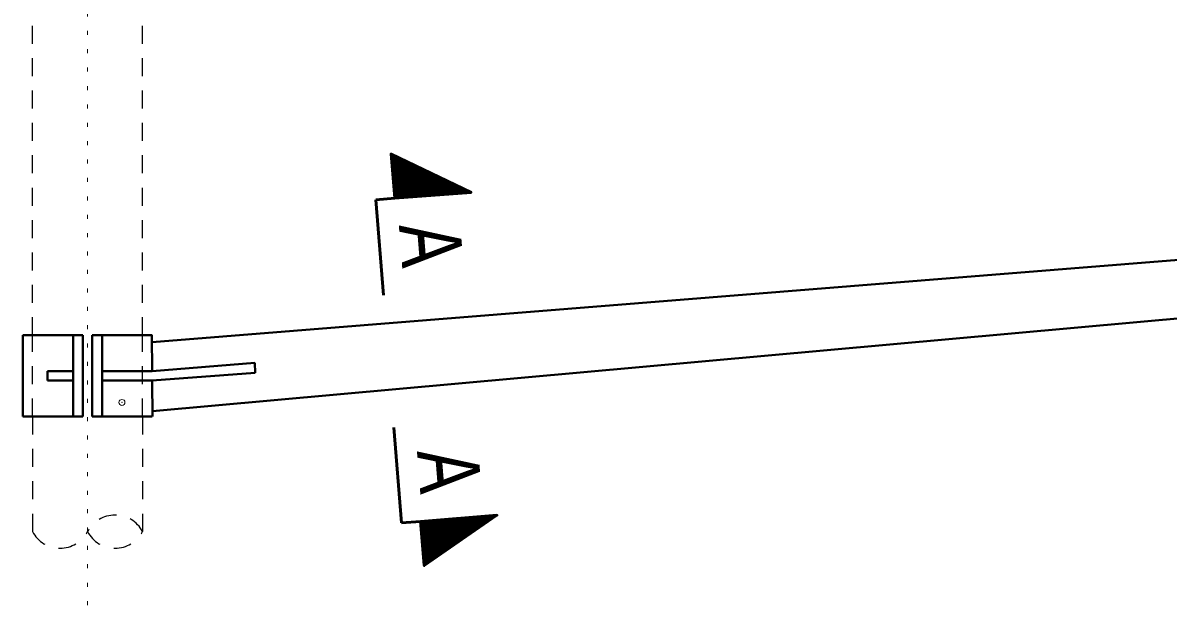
# Model space of a CAD drawing. Extents: x 312583 to 312854, y 144419 to 144597.
# Drawn here: x 312708.98 to 312737.61, y 144536.85 to 144551.41 of the extents above; entities that cross this region are included whole.
import ezdxf
from ezdxf.enums import TextEntityAlignment as Align

# ---------------------------------------------------------------- set-up
doc = ezdxf.new("R2010")
doc.units = 0
doc.header["$LTSCALE"] = 0.3
doc.header["$PDMODE"] = 32
doc.header["$PDSIZE"] = 0.15
doc.linetypes.add('DOTTED', pattern=[1.5, 0.3, -1.2])
doc.linetypes.add('SHORT_DASHED', pattern=[2.7, 1.5, -1.2])
doc.layers.add('1', color=7, linetype='Continuous', lineweight=35)
doc.layers.add('2', color=7, linetype='Continuous', lineweight=13)

msp = doc.modelspace()

# ---------------------------------------------------------------- linework, layer by layer
at = {"layer": '1', "linetype": 'DOTTED', "lineweight": 13}
msp.add_line((312710.5956, 144536.8489), (312710.5956, 144562.3636), dxfattribs=at)
at = {"layer": '1', "linetype": 'SHORT_DASHED', "lineweight": 25}
for p, q in [((312709.2156, 144543.5956), (312709.2156, 144555.9389)), ((312711.9679, 144543.5956), (312711.9679, 144555.9389)), ((312709.2156, 144541.5639), (312709.2156, 144543.5956)), ((312711.9679, 144541.5639), (312711.9679, 144543.5956)), ((312709.2156, 144541.5639), (312709.2156, 144538.6889)), ((312711.9679, 144541.5639), (312711.9679, 144538.6889))]:
    msp.add_line(p, q, dxfattribs=at)
at = {"layer": '1', "lineweight": 40}
for p, q in [((312712.2132, 144543.4269), (312791.0956, 144549.7443)), ((312712.2209, 144541.6943), (312791.0956, 144548.8319)), ((312708.9779, 144543.5956), (312710.4729, 144543.5956)), ((312708.9779, 144542.5759), (312708.9779, 144543.5956)), ((312710.2352, 144542.5759), (312710.2352, 144543.5956)), ((312710.4729, 144542.5759), (312710.4729, 144543.5956)), ((312712.2132, 144543.5956), (312710.7106, 144543.5956)), ((312710.7106, 144542.5759), (312710.7106, 144543.5956)), ((312710.9559, 144542.5759), (312710.9559, 144543.5956)), ((312712.1979, 144543.5956), (312712.2132, 144542.6986)), ((312709.5912, 144542.6986), (312709.5912, 144542.4609)), ((312710.2352, 144542.6986), (312709.5912, 144542.6986)), ((312712.2132, 144542.6986), (312710.9559, 144542.6986)), ((312712.2132, 144542.6986), (312714.7739, 144542.9056)), ((312712.2132, 144542.4609), (312714.7892, 144542.6603)), ((312714.7739, 144542.9056), (312714.7892, 144542.6603)), ((312708.9779, 144542.5759), (312708.9779, 144541.5639)), ((312710.2352, 144542.4609), (312709.5912, 144542.4609)), ((312710.2352, 144542.5759), (312710.2352, 144541.5639)), ((312710.4729, 144542.5759), (312710.4729, 144541.5639)), ((312710.7106, 144542.5759), (312710.7106, 144541.5639)), ((312710.9559, 144542.5759), (312710.9559, 144541.5639)), ((312712.2286, 144542.4609), (312710.9559, 144542.4609)), ((312712.2132, 144542.4533), (312712.2209, 144541.5639))]:
    msp.add_line(p, q, dxfattribs=at)
at = {"layer": '1'}
for p, q in [((312718.1856, 144548.0959), (312718.2009, 144548.1113)), ((312718.1932, 144548.0499), (312718.2239, 144548.1036)), ((312718.2009, 144547.9963), (312718.2469, 144548.0959)), ((312718.2009, 144547.9503), (312718.2699, 144548.0806)), ((312718.2086, 144547.8966), (312718.2929, 144548.0729)), ((312718.2086, 144547.8583), (312718.3082, 144548.0576)), ((312718.2162, 144547.8046), (312718.3312, 144548.0576)), ((312718.2162, 144547.7586), (312718.3542, 144548.0423)), ((312718.2162, 144547.7126), (312718.3696, 144548.0346)), ((312718.2239, 144547.6666), (312718.4002, 144548.0193)), ((312718.2316, 144547.6129), (312718.4156, 144548.0116)), ((312718.2316, 144547.5669), (312718.4462, 144548.0039)), ((312718.2392, 144547.5209), (312718.4692, 144547.9963)), ((312718.2392, 144547.4673), (312718.4846, 144547.9809)), ((312718.2469, 144547.4213), (312718.5076, 144547.9733)), ((312718.2469, 144547.3753), (312718.5229, 144547.9579)), ((312718.2546, 144547.3216), (312718.5459, 144547.9503)), ((312718.2546, 144547.2756), (312718.5689, 144547.9426)), ((312718.2622, 144547.2296), (312718.5842, 144547.9273)), ((312718.2622, 144547.1836), (312718.6149, 144547.9119)), ((312718.2699, 144547.1299), (312718.6379, 144547.9119)), ((312718.2699, 144547.0993), (312718.6532, 144547.8966)), ((312718.2776, 144547.0456), (312718.6839, 144547.8889)), ((312718.2929, 144547.0226), (312718.6992, 144547.8736)), ((312718.3236, 144547.0226), (312718.7222, 144547.8736)), ((312718.3542, 144547.0226), (312718.7452, 144547.8583)), ((312718.3772, 144547.0303), (312718.7606, 144547.8506)), ((312718.4079, 144547.0303), (312718.7836, 144547.8353)), ((312718.4309, 144547.0379), (312718.8142, 144547.8276)), ((312718.4616, 144547.0379), (312718.8296, 144547.8199)), ((312718.4846, 144547.0379), (312718.8526, 144547.8123)), ((312718.5152, 144547.0379), (312718.8756, 144547.7969)), ((312718.5459, 144547.0379), (312718.8909, 144547.7816)), ((312718.5689, 144547.0456), (312718.9139, 144547.7739)), ((312718.5996, 144547.0456), (312718.9369, 144547.7663)), ((312718.6302, 144547.0456), (312718.9599, 144547.7509)), ((312718.6532, 144547.0456), (312718.9752, 144547.7433)), ((312718.6839, 144547.0609), (312719.0059, 144547.7279)), ((312718.7146, 144547.0533), (312719.0289, 144547.7279)), ((312718.7376, 144547.0533), (312719.0442, 144547.7126)), ((312718.7606, 144547.0609), (312719.0672, 144547.7049)), ((312718.7912, 144547.0609), (312719.0902, 144547.6896)), ((312718.8219, 144547.0609), (312719.1056, 144547.6819)), ((312718.8449, 144547.0686), (312719.1286, 144547.6743)), ((312718.8756, 144547.0686), (312719.1516, 144547.6666)), ((312718.8986, 144547.0686), (312719.1746, 144547.6513)), ((312718.9216, 144547.0763), (312719.2052, 144547.6436)), ((312718.9522, 144547.0763), (312719.2206, 144547.6359)), ((312718.9752, 144547.0763), (312719.2436, 144547.6206)), ((312719.0059, 144547.0763), (312719.2666, 144547.6129)), ((312719.0366, 144547.0839), (312719.2819, 144547.5976)), ((312719.0596, 144547.0839), (312719.3049, 144547.5899)), ((312719.0902, 144547.0839), (312719.3279, 144547.5823)), ((312719.1209, 144547.0839), (312719.3432, 144547.5746)), ((312719.1439, 144547.0916), (312719.3739, 144547.5593)), ((312719.1746, 144547.0916), (312719.3969, 144547.5516)), ((312719.2052, 144547.0916), (312719.4122, 144547.5439)), ((312719.2282, 144547.0993), (312719.4352, 144547.5363)), ((312719.2512, 144547.0993), (312719.4582, 144547.5209)), ((312719.2819, 144547.0993), (312719.4812, 144547.5133)), ((312719.3126, 144547.0993), (312719.4966, 144547.4979)), ((312719.3432, 144547.1069), (312719.5196, 144547.4903)), ((312719.3662, 144547.1069), (312719.5426, 144547.4826)), ((312719.3969, 144547.1069), (312719.5656, 144547.4673)), ((312719.4199, 144547.1146), (312719.5886, 144547.4519)), ((312719.4506, 144547.1146), (312719.6116, 144547.4519)), ((312719.4736, 144547.1146), (312719.6269, 144547.4366)), ((312719.5042, 144547.1146), (312719.6499, 144547.4289)), ((312719.5349, 144547.1223), (312719.6729, 144547.4136)), ((312719.5579, 144547.1223), (312719.6882, 144547.4059)), ((312719.5886, 144547.1223), (312719.7189, 144547.3983)), ((312719.6116, 144547.1223), (312719.7419, 144547.3906)), ((312719.6422, 144547.1299), (312719.7649, 144547.3753)), ((312719.6729, 144547.1299), (312719.7879, 144547.3676)), ((312719.6959, 144547.1299), (312719.8032, 144547.3599)), ((312719.7266, 144547.1376), (312719.8262, 144547.3523)), ((312719.7496, 144547.1376), (312719.8492, 144547.3369)), ((312719.7802, 144547.1376), (312719.8646, 144547.3216)), ((312719.8109, 144547.1453), (312719.8876, 144547.3139)), ((312719.8416, 144547.1453), (312719.9106, 144547.3063)), ((312719.8646, 144547.1453), (312719.9336, 144547.2909)), ((312719.8952, 144547.1453), (312719.9566, 144547.2833)), ((312719.9182, 144547.1529), (312719.9796, 144547.2679)), ((312719.9412, 144547.1529), (312720.0026, 144547.2679)), ((312719.9719, 144547.1529), (312720.0179, 144547.2526)), ((312720.0026, 144547.1606), (312720.0409, 144547.2449)), ((312720.0332, 144547.1606), (312720.0639, 144547.2296)), ((312720.0562, 144547.1606), (312720.0792, 144547.2219)), ((312720.0869, 144547.1606), (312720.1099, 144547.2143)), ((312720.1099, 144547.1683), (312720.1329, 144547.2066)), ((312720.1406, 144547.1683), (312720.1482, 144547.1913)), ((312720.1712, 144547.1683), (312720.1712, 144547.1836)), ((312718.9216, 144538.9189), (312719.4659, 144538.1523)), ((312718.9369, 144538.9496), (312719.4736, 144538.1676)), ((312718.9676, 144538.9496), (312719.4966, 144538.1753)), ((312718.9982, 144538.9496), (312719.5196, 144538.1906)), ((312719.0212, 144538.9496), (312719.5349, 144538.1983)), ((312719.0519, 144538.9573), (312719.5579, 144538.2213)), ((312719.0749, 144538.9496), (312719.5809, 144538.2289)), ((312719.1056, 144538.9496), (312719.5962, 144538.2443)), ((312719.1286, 144538.9649), (312719.6116, 144538.2519)), ((312719.1592, 144538.9649), (312719.6346, 144538.2749)), ((312719.1899, 144538.9649), (312719.6499, 144538.2903)), ((312719.2129, 144538.9649), (312719.6729, 144538.2979)), ((312719.2436, 144538.9726), (312719.6959, 144538.3133)), ((312719.2742, 144538.9726), (312719.7189, 144538.3286)), ((312719.2972, 144538.9726), (312719.7342, 144538.3439)), ((312719.3279, 144538.9726), (312719.7496, 144538.3593)), ((312719.3586, 144538.9803), (312719.7726, 144538.3669)), ((312719.3816, 144538.9803), (312719.7879, 144538.3823)), ((312719.4046, 144538.9803), (312719.8109, 144538.3899)), ((312719.4352, 144538.9879), (312719.8339, 144538.4129)), ((312719.4659, 144538.9879), (312719.8492, 144538.4206)), ((312719.4966, 144538.9879), (312719.8722, 144538.4359)), ((312719.5196, 144538.9956), (312719.8952, 144538.4436)), ((312719.5502, 144538.9956), (312719.9029, 144538.4589)), ((312719.5732, 144538.9879), (312719.9336, 144538.4743)), ((312719.6039, 144538.9956), (312719.9489, 144538.4896)), ((312719.6269, 144539.0033), (312719.9719, 144538.5049)), ((312719.6576, 144539.0033), (312719.9949, 144538.5126)), ((312719.6882, 144539.0033), (312720.0102, 144538.5279)), ((312719.7112, 144539.0109), (312720.0332, 144538.5433)), ((312719.7419, 144539.0109), (312720.0562, 144538.5586)), ((312719.7726, 144539.0109), (312720.0639, 144538.5663)), ((312719.7956, 144539.0109), (312720.0869, 144538.5816)), ((312719.8262, 144539.0186), (312720.1099, 144538.5969)), ((312719.8569, 144539.0186), (312720.1252, 144538.6123)), ((312719.8799, 144539.0186), (312720.1482, 144538.6199)), ((312719.9029, 144539.0263), (312720.1712, 144538.6353)), ((312719.9336, 144539.0263), (312720.1942, 144538.6429)), ((312719.9642, 144539.0263), (312720.2096, 144538.6659)), ((312719.9949, 144539.0339), (312720.2249, 144538.6813)), ((312720.0179, 144539.0339), (312720.2479, 144538.6889)), ((312720.0486, 144539.0339), (312720.2632, 144538.7043)), ((312720.0716, 144539.0339), (312720.2862, 144538.7196)), ((312720.1022, 144539.0416), (312720.3092, 144538.7349)), ((312720.1176, 144539.0416), (312720.3246, 144538.7503)), ((312720.1482, 144539.0416), (312720.3476, 144538.7579)), ((312720.1866, 144539.0416), (312720.3629, 144538.7733)), ((312720.2019, 144539.0493), (312720.3782, 144538.7809)), ((312720.2326, 144539.0493), (312720.4089, 144538.8039)), ((312720.2556, 144539.0493), (312720.4242, 144538.8116)), ((312720.2862, 144539.0569), (312720.4472, 144538.8269)), ((312720.3169, 144539.0569), (312720.4702, 144538.8346)), ((312720.3399, 144539.0569), (312720.4856, 144538.8576)), ((312720.3706, 144539.0569), (312720.5086, 144538.8653)), ((312720.3936, 144539.0646), (312720.5239, 144538.8806)), ((312720.4242, 144539.0646), (312720.5392, 144538.8959)), ((312720.4549, 144539.0646), (312720.5622, 144538.9036)), ((312720.4856, 144539.0723), (312720.5852, 144538.9266)), ((312720.5086, 144539.0723), (312720.6006, 144538.9419)), ((312720.5392, 144539.0723), (312720.6236, 144538.9496)), ((312720.5622, 144539.0723), (312720.6389, 144538.9649)), ((312720.5852, 144539.0799), (312720.6619, 144538.9803)), ((312720.6159, 144539.0799), (312720.6772, 144538.9956)), ((312720.6466, 144539.0799), (312720.7002, 144539.0033)), ((312720.6772, 144539.0876), (312720.7232, 144539.0186)), ((312720.7002, 144539.0876), (312720.7386, 144539.0263)), ((312720.7309, 144539.0876), (312720.7616, 144539.0493)), ((312720.7539, 144539.0876), (312720.7846, 144539.0569)), ((312720.7846, 144539.0953), (312720.7922, 144539.0723)), ((312720.8152, 144539.0953), (312720.8152, 144539.0799)), ((312718.9292, 144538.8653), (312719.4352, 144538.1369)), ((312718.9292, 144538.8269), (312719.4199, 144538.1216)), ((312718.9369, 144538.7733), (312719.3969, 144538.1139)), ((312718.9369, 144538.7273), (312719.3739, 144538.0986)), ((312718.9446, 144538.6813), (312719.3586, 144538.0833)), ((312718.9446, 144538.6353), (312719.3356, 144538.0679)), ((312718.9522, 144538.5893), (312719.3126, 144538.0526)), ((312718.9522, 144538.5433), (312719.3049, 144538.0373)), ((312718.9599, 144538.4973), (312719.2819, 144538.0296)), ((312718.9599, 144538.4436), (312719.2666, 144538.0143)), ((312718.9676, 144538.3976), (312719.2436, 144537.9989)), ((312718.9676, 144538.3516), (312719.2206, 144537.9836)), ((312718.9752, 144538.2979), (312719.2052, 144537.9759)), ((312718.9752, 144538.2519), (312719.1746, 144537.9606)), ((312718.9829, 144538.2059), (312719.1669, 144537.9453)), ((312718.9829, 144538.1599), (312719.1439, 144537.9299)), ((312718.9906, 144538.1063), (312719.1209, 144537.9223)), ((312718.9906, 144538.0679), (312719.1056, 144537.9069)), ((312718.9982, 144538.0143), (312719.0826, 144537.8993)), ((312718.9982, 144537.9683), (312719.0596, 144537.8763)), ((312719.0059, 144537.9146), (312719.0442, 144537.8609)), ((312719.0059, 144537.8686), (312719.0212, 144537.8533))]:
    msp.add_line(p, q, dxfattribs=at)
at = {"layer": '1', "lineweight": 53}
for p, q in [((312718.2776, 144547.0226), (312717.8022, 144546.9843)), ((312717.9939, 144544.5999), (312717.8022, 144546.9843)), ((312718.2546, 144541.2879), (312718.4462, 144538.9036)), ((312718.9216, 144538.9419), (312718.4462, 144538.9036))]:
    msp.add_line(p, q, dxfattribs=at)
for points in [[(312718.2776, 144547.0226), (312718.1856, 144548.1266), (312720.1866, 144547.1683)], [(312718.9216, 144538.9419), (312719.0136, 144537.8379), (312720.8306, 144539.0953)]]:
    msp.add_lwpolyline(points, close=True, dxfattribs=at)
at = {"layer": '1', "lineweight": 40}
for points in [[(312708.9779, 144541.5639), (312710.2352, 144541.5639), (312710.4729, 144541.5639)], [(312712.2132, 144541.5639), (312710.9559, 144541.5639), (312710.7106, 144541.5639)]]:
    msp.add_lwpolyline(points, dxfattribs=at)
at = {"layer": '1', "linetype": 'SHORT_DASHED', "lineweight": 25}
for centre, start, end in [((312711.282, 144538.3208), 27.93563, 152.06437), ((312709.9044, 144539.0513), 207.93563, 332.06437), ((312711.282, 144539.0513), 207.93563, 332.06437)]:
    msp.add_arc(centre, 0.7796, start, end, dxfattribs=at)
at = {"layer": '2'}
msp.add_point((312711.4542, 144541.9166), dxfattribs=at)

# ---------------------------------------------------------------- texts
at = {"layer": '1', "width": 0.8}
for p in [(312718.4216, 144545.8015), (312718.874, 144540.1512)]:
    msp.add_text('A', height=1.533, rotation=274.577, dxfattribs=at).set_placement(p, align=Align.CENTER)

doc.saveas('drawing.dxf')
